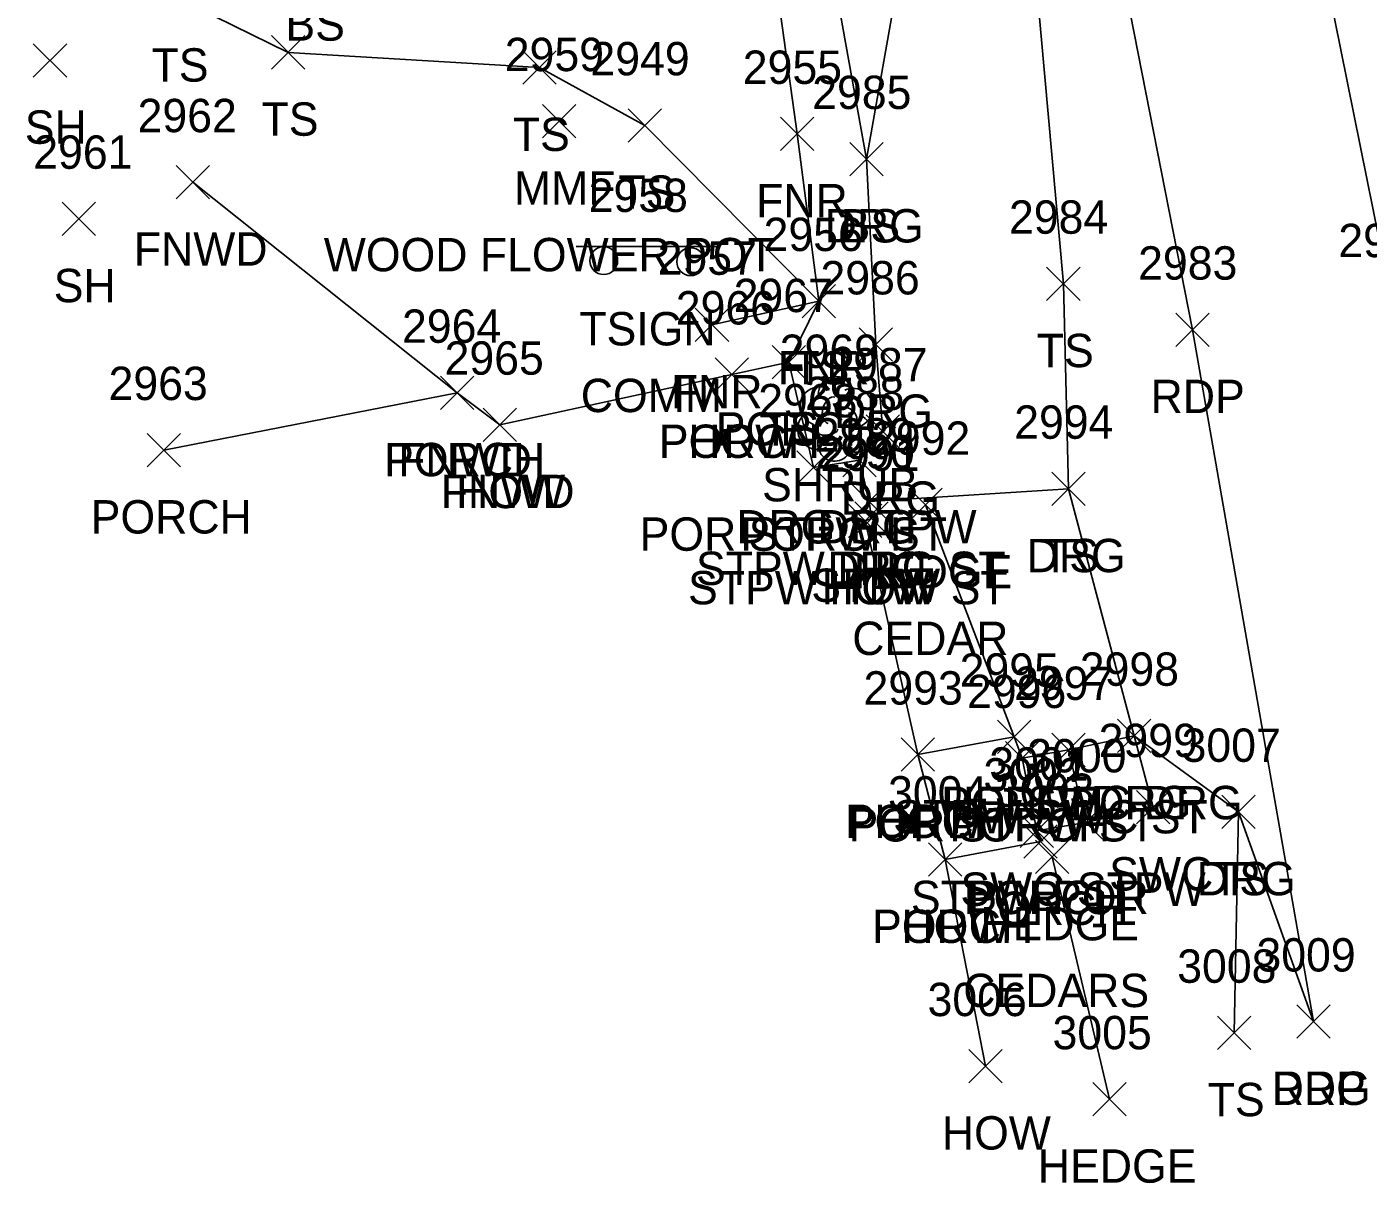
# Model space of a CAD drawing. Extents: x 1504228 to 1506103, y 437717 to 440106.
# Drawn here: x 1505191.7 to 1505272.1, y 437902.8 to 437972.2 of the extents above; entities that cross this region are included whole.
import ezdxf

# ---------------------------------------------------------------- set-up
doc = ezdxf.new("R2010")
doc.units = 0
for name, color, linetype in [('L_A', 7, 'Continuous'), ('L_C', 7, 'Continuous'), ('L_I', 7, 'Continuous'), ('L_TIC', 7, 'Continuous'), ('LAHR', 7, 'Continuous'), ('LBC', 7, 'Continuous'), ('LBF', 7, 'Continuous'), ('LELB', 7, 'Continuous'), ('LFNC', 7, 'Continuous'), ('LSH', 7, 'Continuous'), ('P_A', 7, 'Continuous'), ('P_I', 7, 'Continuous'), ('P_TIC', 7, 'Continuous'), ('PET', 7, 'Continuous'), ('PRC', 7, 'Continuous'), ('R_A', 7, 'Continuous'), ('R_I', 7, 'Continuous'), ('R_TIC', 7, 'Continuous'), ('RDG', 7, 'Continuous'), ('RSW', 7, 'Continuous'), ('S_A', 7, 'Continuous'), ('S_C', 7, 'Continuous'), ('S_I', 7, 'Continuous'), ('SSGN', 7, 'Continuous')]:
    doc.layers.add(name, color=color, linetype=linetype)

msp = doc.modelspace()

# ---------------------------------------------------------------- linework, layer by layer
at = {"layer": 'L_TIC'}
for points in [[(1505192.056, 437969.158), (1505194.056, 437971.158)], [(1505194.056, 437969.158), (1505192.056, 437971.158)], [(1505206.329, 437969.64), (1505208.329, 437971.64)], [(1505208.329, 437969.64), (1505206.329, 437971.64)], [(1505221.396, 437968.728), (1505223.396, 437970.728)], [(1505223.396, 437968.728), (1505221.396, 437970.728)], [(1505222.587, 437965.513), (1505224.587, 437967.513)], [(1505224.587, 437965.513), (1505222.587, 437967.513)], [(1505227.724, 437965.261), (1505229.724, 437967.261)], [(1505229.724, 437965.261), (1505227.724, 437967.261)], [(1505236.851, 437964.748), (1505238.851, 437966.748)], [(1505238.851, 437964.748), (1505236.851, 437966.748)], [(1505241.012, 437963.241), (1505243.012, 437965.241)], [(1505243.012, 437963.241), (1505241.012, 437965.241)], [(1505200.614, 437961.852), (1505202.614, 437963.852)], [(1505202.614, 437961.852), (1505200.614, 437963.852)], [(1505193.79, 437959.659), (1505195.79, 437961.659)], [(1505195.79, 437959.659), (1505193.79, 437961.659)], [(1505252.81, 437955.765), (1505254.81, 437957.765)], [(1505254.81, 437955.765), (1505252.81, 437957.765)], [(1505238.153, 437954.727), (1505240.153, 437956.727)], [(1505240.153, 437954.727), (1505238.153, 437956.727)], [(1505238.153, 437954.727), (1505240.153, 437956.727)], [(1505240.153, 437954.727), (1505238.153, 437956.727)], [(1505231.745, 437953.304), (1505233.745, 437955.304)], [(1505233.745, 437953.304), (1505231.745, 437955.304)], [(1505236.349, 437951.065), (1505238.349, 437953.065)], [(1505238.349, 437951.065), (1505236.349, 437953.065)], [(1505236.349, 437951.065), (1505238.349, 437953.065)], [(1505238.349, 437951.065), (1505236.349, 437953.065)], [(1505232.936, 437950.323), (1505234.936, 437952.323)], [(1505234.936, 437950.323), (1505232.936, 437952.323)], [(1505232.936, 437950.323), (1505234.936, 437952.323)], [(1505234.936, 437950.323), (1505232.936, 437952.323)], [(1505216.468, 437949.226), (1505218.468, 437951.226)], [(1505218.468, 437949.226), (1505216.468, 437951.226)], [(1505216.468, 437949.226), (1505218.468, 437951.226)], [(1505218.468, 437949.226), (1505216.468, 437951.226)], [(1505219.019, 437947.314), (1505221.019, 437949.314)], [(1505221.019, 437947.314), (1505219.019, 437949.314)], [(1505219.019, 437947.314), (1505221.019, 437949.314)], [(1505221.019, 437947.314), (1505219.019, 437949.314)], [(1505198.873, 437945.793), (1505200.873, 437947.793)], [(1505200.873, 437945.793), (1505198.873, 437947.793)], [(1505240.583, 437945.196), (1505242.583, 437947.196)], [(1505242.583, 437945.196), (1505240.583, 437947.196)], [(1505237.824, 437944.759), (1505239.824, 437946.759)], [(1505239.824, 437944.759), (1505237.824, 437946.759)], [(1505237.824, 437944.759), (1505239.824, 437946.759)], [(1505239.824, 437944.759), (1505237.824, 437946.759)], [(1505253.123, 437943.473), (1505255.123, 437945.473)], [(1505255.123, 437943.473), (1505253.123, 437945.473)], [(1505241.169, 437942.707), (1505243.169, 437944.707)], [(1505243.169, 437942.707), (1505241.169, 437944.707)], [(1505244.54, 437942.511), (1505246.54, 437944.511)], [(1505246.54, 437942.511), (1505244.54, 437944.511)], [(1505240.93, 437941.546), (1505242.93, 437943.546)], [(1505242.93, 437941.546), (1505240.93, 437943.546)], [(1505240.93, 437941.546), (1505242.93, 437943.546)], [(1505242.93, 437941.546), (1505240.93, 437943.546)], [(1505241.304, 437941.69), (1505243.304, 437943.69)], [(1505243.304, 437941.69), (1505241.304, 437943.69)], [(1505249.854, 437928.607), (1505251.854, 437930.607)], [(1505251.854, 437928.607), (1505249.854, 437930.607)], [(1505249.854, 437928.607), (1505251.854, 437930.607)], [(1505251.854, 437928.607), (1505249.854, 437930.607)], [(1505244.09, 437927.537), (1505246.09, 437929.537)], [(1505246.09, 437927.537), (1505244.09, 437929.537)], [(1505244.09, 437927.537), (1505246.09, 437929.537)], [(1505246.09, 437927.537), (1505244.09, 437929.537)], [(1505250.35, 437927.329), (1505252.35, 437929.329)], [(1505252.35, 437927.329), (1505250.35, 437929.329)], [(1505250.35, 437927.329), (1505252.35, 437929.329)], [(1505252.35, 437927.329), (1505250.35, 437929.329)], [(1505253.117, 437927.815), (1505255.117, 437929.815)], [(1505255.117, 437927.815), (1505253.117, 437929.815)], [(1505263.316, 437924.103), (1505265.316, 437926.103)], [(1505265.316, 437924.103), (1505263.316, 437926.103)], [(1505254.148, 437923.471), (1505256.148, 437925.471)], [(1505256.148, 437923.471), (1505254.148, 437925.471)], [(1505251.222, 437922.976), (1505253.222, 437924.976)], [(1505253.222, 437922.976), (1505251.222, 437924.976)], [(1505251.222, 437922.976), (1505253.222, 437924.976)], [(1505253.222, 437922.976), (1505251.222, 437924.976)], [(1505251.437, 437922.326), (1505253.437, 437924.326)], [(1505253.437, 437922.326), (1505251.437, 437924.326)], [(1505245.719, 437921.245), (1505247.719, 437923.245)], [(1505247.719, 437921.245), (1505245.719, 437923.245)], [(1505245.719, 437921.245), (1505247.719, 437923.245)], [(1505247.719, 437921.245), (1505245.719, 437923.245)], [(1505252.132, 437921.401), (1505254.132, 437923.401)], [(1505254.132, 437921.401), (1505252.132, 437923.401)], [(1505263.054, 437910.858), (1505265.054, 437912.858)], [(1505265.054, 437910.858), (1505263.054, 437912.858)], [(1505248.143, 437908.86), (1505250.143, 437910.86)], [(1505250.143, 437908.86), (1505248.143, 437910.86)], [(1505255.58, 437906.873), (1505257.58, 437908.873)], [(1505257.58, 437906.873), (1505255.58, 437908.873)]]:
    msp.add_lwpolyline(points, dxfattribs=at)
at = {"layer": 'LAHR'}
for points in [[(1505245.54, 437943.511), (1505250.854, 437929.607)], [(1505253.132, 437922.401), (1505256.58, 437907.873)]]:
    msp.add_lwpolyline(points, dxfattribs=at)
at = {"layer": 'LBC'}
for points in [[(1505220.019, 437948.314), (1505233.936, 437951.323)], [(1505241.93, 437942.546), (1505245.09, 437928.537), (1505246.719, 437922.245), (1505249.143, 437909.86)]]:
    msp.add_lwpolyline(points, dxfattribs=at)
at = {"layer": 'LBF'}
for points in [[(1505233.936, 437951.323), (1505237.349, 437952.065), (1505238.824, 437945.759)], [(1505199.873, 437946.793), (1505217.468, 437950.226)], [(1505238.824, 437945.759), (1505241.583, 437946.196), (1505242.169, 437943.707), (1505242.304, 437942.69), (1505241.93, 437942.546)], [(1505245.09, 437928.537), (1505250.854, 437929.607), (1505251.35, 437928.329), (1505252.222, 437923.976), (1505252.437, 437923.326), (1505246.719, 437922.245)], [(1505251.35, 437928.329), (1505254.117, 437928.815), (1505255.148, 437924.471), (1505252.222, 437923.976)]]:
    msp.add_lwpolyline(points, dxfattribs=at)
at = {"layer": 'LELB'}
for points in [[(1505216.601, 438137.556), (1505223.944, 438121.386), (1505226.122, 438115.183), (1505227.826, 438097.732), (1505234.433, 438067.787), (1505241.158, 438043.279), (1505244.446, 438026.005), (1505250.203, 437996.886), (1505253.81, 437956.765), (1505254.123, 437944.473)], [(1505216.575, 438127.724), (1505214.625, 438113.719), (1505216.782, 438101.678), (1505215.58, 438085.68), (1505222.54, 438071.184), (1505228.277, 438057.902), (1505236.701, 438043.311), (1505240.058, 438029.465), (1505242.84, 438013.821), (1505243.246, 437995.871), (1505245.516, 437984.141), (1505242.012, 437964.241)], [(1505200.521, 437982.869), (1505200.733, 437973.884), (1505207.329, 437970.64), (1505222.396, 437969.728), (1505228.724, 437966.261), (1505239.153, 437955.727), (1505237.349, 437952.065)], [(1505264.316, 437925.103), (1505264.054, 437911.858)]]:
    msp.add_lwpolyline(points, dxfattribs=at)
at = {"layer": 'LFNC'}
for points in [[(1505193.634, 437989.407), (1505201.282, 437990.707), (1505219.361, 437993.839), (1505234.026, 437996.905), (1505235.671, 437981.467), (1505237.851, 437965.748), (1505239.153, 437955.727), (1505232.745, 437954.304)], [(1505201.614, 437962.852), (1505217.468, 437950.226), (1505220.019, 437948.314)]]:
    msp.add_lwpolyline(points, dxfattribs=at)
at = {"layer": 'LSH'}
msp.add_line((1505240.119, 437948.719), (1505240.119, 437948.719), dxfattribs=at)
msp.add_line((1505240.119, 437948.719), (1505240.119, 437948.719), dxfattribs=at)
msp.add_arc((1505240.166, 437950.153), 1.047, 335.52715, 180.95627, dxfattribs=at)
for centre, major_axis, ratio, start_param, end_param in [((1505239.328, 437949.386), (1.21, -0.512), 0.895232, 1.570796, 4.712389), ((1505241.161, 437949.303), (-1.141, -0.483), 0.949671, 1.570796, 4.712389), ((1505239.911, 437949.178), (-0.208, -0.792), 0.645439, 3.141593, 6.283185), ((1505240.619, 437948.553), (-0.5, 0.667), 0.989748, 3.141593, 6.283185), ((1505239.036, 437948.011), (0.584, -1.042), 0.959034, 3.141593, 6.283185), ((1505241.119, 437947.886), (-1.09, 0.792), 0.841452, 1.570796, 4.712389), ((1505239.661, 437947.969), (-0.625, -0.083), 0.423636, 0, 3.141593), ((1505240.12, 437947.219), (0.265, 1.061), 0.942809, 1.570796, 4.712389)]:
    msp.add_ellipse(centre, major_axis=major_axis, ratio=ratio, start_param=start_param, end_param=end_param, dxfattribs=at)
at = {"layer": 'P_TIC'}
for points in [[(1505260.553, 437953.013), (1505262.553, 437955.013)], [(1505262.553, 437953.013), (1505260.553, 437955.013)], [(1505267.813, 437911.533), (1505269.813, 437913.533)], [(1505269.813, 437911.533), (1505267.813, 437913.533)]]:
    msp.add_lwpolyline(points, dxfattribs=at)
at = {"layer": 'PET'}
msp.add_lwpolyline([(1505219.541, 438139.332), (1505225.977, 438121.196), (1505231.004, 438101.796), (1505238.496, 438063.959), (1505242.844, 438043.923), (1505252.224, 438001.481), (1505261.553, 437954.013), (1505268.813, 437912.533)], dxfattribs=at)
at = {"layer": 'PRC'}
msp.add_lwpolyline([(1505229.478, 438143.453), (1505234.695, 438118.095), (1505243.623, 438084.856), (1505253.152, 438053.473), (1505260.454, 438023.846), (1505266.195, 437991.874), (1505273.558, 437955.361), (1505281.379, 437913.196)], dxfattribs=at)
at = {"layer": 'R_TIC'}
for points in [[(1505241.012, 437963.241), (1505243.012, 437965.241)], [(1505243.012, 437963.241), (1505241.012, 437965.241)], [(1505241.564, 437952.127), (1505243.564, 437954.127)], [(1505243.564, 437952.127), (1505241.564, 437954.127)], [(1505241.98, 437946.915), (1505243.98, 437948.915)], [(1505243.98, 437946.915), (1505241.98, 437948.915)], [(1505240.583, 437945.196), (1505242.583, 437947.196)], [(1505242.583, 437945.196), (1505240.583, 437947.196)], [(1505253.123, 437943.473), (1505255.123, 437945.473)], [(1505255.123, 437943.473), (1505253.123, 437945.473)], [(1505241.169, 437942.707), (1505243.169, 437944.707)], [(1505243.169, 437942.707), (1505241.169, 437944.707)], [(1505257.054, 437928.664), (1505259.054, 437930.664)], [(1505259.054, 437928.664), (1505257.054, 437930.664)], [(1505257.054, 437928.664), (1505259.054, 437930.664)], [(1505259.054, 437928.664), (1505257.054, 437930.664)], [(1505253.117, 437927.815), (1505255.117, 437929.815)], [(1505255.117, 437927.815), (1505253.117, 437929.815)], [(1505258.195, 437924.39), (1505260.195, 437926.39)], [(1505260.195, 437924.39), (1505258.195, 437926.39)], [(1505263.316, 437924.103), (1505265.316, 437926.103)], [(1505265.316, 437924.103), (1505263.316, 437926.103)], [(1505254.148, 437923.471), (1505256.148, 437925.471)], [(1505256.148, 437923.471), (1505254.148, 437925.471)], [(1505267.813, 437911.533), (1505269.813, 437913.533)], [(1505269.813, 437911.533), (1505267.813, 437913.533)]]:
    msp.add_lwpolyline(points, dxfattribs=at)
at = {"layer": 'RDG'}
for points in [[(1505252.224, 438001.481), (1505250.203, 437996.886), (1505245.516, 437984.141), (1505239.029, 437980.808), (1505242.012, 437964.241), (1505242.564, 437953.127), (1505242.98, 437947.915), (1505241.583, 437946.196)], [(1505242.169, 437943.707), (1505254.123, 437944.473), (1505258.054, 437929.664), (1505264.316, 437925.103), (1505268.813, 437912.533)]]:
    msp.add_lwpolyline(points, dxfattribs=at)
at = {"layer": 'RSW'}
msp.add_lwpolyline([(1505254.117, 437928.815), (1505258.054, 437929.664), (1505259.195, 437925.39), (1505255.148, 437924.471)], dxfattribs=at)
at = {"layer": 'SSGN'}
for p, q in [((1505224.593, 437958.991), (1505233.19, 437958.991)), ((1505228.615, 437958.087), (1505228.615, 437958.087))]:
    msp.add_line(p, q, dxfattribs=at)
for centre in [(1505226.254, 437958.158), (1505231.469, 437958.087)]:
    msp.add_circle(centre, 0.833, dxfattribs=at)

# ---------------------------------------------------------------- texts
at = {"layer": 'L_A'}
for s, p in [('BS', (1505207.169, 437971.338)), ('TS', (1505199.143, 437968.884)), ('SH', (1505191.545, 437965.158)), ('TS', (1505205.738, 437965.64)), ('TS', (1505220.805, 437964.728)), ('MMF', (1505220.871, 437961.513)), ('TS', (1505227.133, 437961.261)), ('FNR', (1505235.387, 437960.748)), ('BS', (1505240.453, 437959.241)), ('FNWD', (1505198.079, 437957.852)), ('SH', (1505193.278, 437955.659)), ('TS', (1505252.22, 437951.765)), ('FNR', (1505236.689, 437950.727)), ('TS', (1505237.563, 437950.727)), ('FNR', (1505230.281, 437949.304)), ('PORCH', (1505232.971, 437947.065)), ('TS', (1505235.758, 437947.065)), ('PORCH', (1505229.558, 437946.323)), ('HOW', (1505231.322, 437946.323)), ('PORCH', (1505213.09, 437945.226)), ('FNWD', (1505213.933, 437945.226)), ('SHRUB', (1505235.749, 437943.719)), ('FNWD', (1505216.483, 437943.314)), ('HOW', (1505217.405, 437943.314)), ('PORCH', (1505195.495, 437941.793)), ('DRG STPW', (1505234.197, 437941.196)), ('POR STPW ST', (1505228.406, 437940.759)), ('PORCH', (1505234.446, 437940.759)), ('TS', (1505252.532, 437939.473)), ('STPW DRG ST', (1505231.783, 437938.707)), ('HEDGE', (1505241.241, 437938.511)), ('STPW HOW ST', (1505231.308, 437937.546)), ('STPW', (1505238.698, 437937.69)), ('HOW', (1505239.316, 437937.546)), ('PORCH', (1505246.476, 437924.607)), ('HEDGE', (1505246.555, 437924.607)), ('PORCH', (1505240.712, 437923.537)), ('POR STPW ST', (1505240.933, 437923.329)), ('HOW', (1505242.476, 437923.537)), ('STPW SWC ST', (1505243.605, 437923.815)), ('PORCH', (1505246.972, 437923.329)), ('TS', (1505262.725, 437920.103)), ('SWC STPW', (1505247.636, 437919.471)), ('STPW POR', (1505244.671, 437918.976)), ('PORCH', (1505247.844, 437918.976)), ('PORCH', (1505248.059, 437918.326)), ('PORCH', (1505242.341, 437917.245)), ('HOW', (1505244.104, 437917.245)), ('HEDGE', (1505248.833, 437917.401)), ('TS', (1505262.464, 437906.858)), ('HOW', (1505246.529, 437904.86)), ('HEDGE', (1505252.281, 437902.873))]:
    msp.add_text(s, height=2, dxfattribs=at).set_placement(p)
at = {"layer": 'L_C'}
for s, p in [('WOOD FLOWER POT', (1505209.469, 437957.513)), ('CEDAR', (1505241.154, 437934.511)), ('CEDARS', (1505247.809, 437913.401))]:
    msp.add_text(s, height=2, dxfattribs=at).set_placement(p)
at = {"layer": 'L_I'}
for s, p in [('2959', (1505220.32, 437969.513)), ('2949', (1505225.456, 437969.261)), ('2955', (1505234.591, 437968.748)), ('2985', (1505238.752, 437967.241)), ('2962', (1505198.307, 437965.852)), ('2961', (1505192.05, 437963.659)), ('2984', (1505250.551, 437959.765)), ('2956', (1505235.838, 437958.727)), ('2956', (1505235.838, 437958.727)), ('2957', (1505229.485, 437957.304)), ('2967', (1505234.042, 437955.065)), ('2967', (1505234.042, 437955.065)), ('2966', (1505230.574, 437954.323)), ('2966', (1505230.574, 437954.323)), ('2964', (1505214.161, 437953.226)), ('2964', (1505214.161, 437953.226)), ('2969', (1505236.804, 437951.719)), ('2965', (1505216.712, 437951.314)), ('2965', (1505216.712, 437951.314)), ('2963', (1505196.566, 437949.793)), ('2988', (1505238.323, 437949.196)), ('2968', (1505235.517, 437948.759)), ('2968', (1505235.517, 437948.759)), ('2994', (1505250.863, 437947.473)), ('2989', (1505238.901, 437946.707)), ('2992', (1505242.28, 437946.511)), ('2990', (1505238.958, 437945.69)), ('2991', (1505239.237, 437945.546)), ('2991', (1505239.237, 437945.546)), ('2995', (1505247.594, 437932.607)), ('2995', (1505247.594, 437932.607)), ('2993', (1505241.83, 437931.537)), ('2993', (1505241.83, 437931.537)), ('2996', (1505248.035, 437931.329)), ('2996', (1505248.035, 437931.329)), ('2997', (1505250.857, 437931.815)), ('3007', (1505260.899, 437928.103)), ('3000', (1505251.644, 437927.471)), ('3001', (1505249.372, 437926.976)), ('3001', (1505249.372, 437926.976)), ('3002', (1505249.019, 437926.326)), ('3004', (1505243.301, 437925.245)), ('3004', (1505243.301, 437925.245)), ('3003', (1505249.714, 437925.401)), ('3008', (1505260.637, 437914.858)), ('3006', (1505245.67, 437912.86)), ('3005', (1505253.163, 437910.873))]:
    msp.add_text(s, height=2, dxfattribs=at).set_placement(p)
at = {"layer": 'P_A'}
for p in [(1505259.041, 437949.013), (1505266.302, 437907.533)]:
    msp.add_text('RDP', height=2, dxfattribs=at).set_placement(p)
at = {"layer": 'P_I'}
for s, p in [('2982', (1505270.298, 437958.361)), ('2983', (1505258.293, 437957.013)), ('3009', (1505265.388, 437915.533))]:
    msp.add_text(s, height=2, dxfattribs=at).set_placement(p)
at = {"layer": 'R_A'}
for s, p in [('DRG', (1505239.5, 437959.241)), ('DRG', (1505240.052, 437948.127)), ('DRG', (1505240.468, 437942.915)), ('DRG', (1505239.071, 437941.196)), ('DRG', (1505251.611, 437939.473)), ('DRG', (1505239.657, 437938.707)), ('SWC DRG', (1505251.636, 437924.664)), ('DRG', (1505255.542, 437924.664)), ('STPW SWC ST', (1505243.605, 437923.815)), ('SWC', (1505256.557, 437920.39)), ('DRG', (1505261.804, 437920.103)), ('SWC STPW', (1505247.636, 437919.471)), ('DRG', (1505266.302, 437907.533))]:
    msp.add_text(s, height=2, dxfattribs=at).set_placement(p)
at = {"layer": 'R_I'}
for s, p in [('2985', (1505238.752, 437967.241)), ('2986', (1505239.249, 437956.127)), ('2987', (1505239.72, 437950.915)), ('2988', (1505238.323, 437949.196)), ('2994', (1505250.863, 437947.473)), ('2989', (1505238.901, 437946.707)), ('2998', (1505254.794, 437932.664)), ('2998', (1505254.794, 437932.664)), ('2997', (1505250.857, 437931.815)), ('2999', (1505255.927, 437928.39)), ('3007', (1505260.899, 437928.103)), ('3000', (1505251.644, 437927.471)), ('3009', (1505265.388, 437915.533))]:
    msp.add_text(s, height=2, dxfattribs=at).set_placement(p)
at = {"layer": 'S_A'}
msp.add_text('TSIGN', height=2, dxfattribs=at).set_placement((1505224.791, 437953.07))
at = {"layer": 'S_C'}
msp.add_text('COMM', height=2, dxfattribs=at).set_placement((1505224.878, 437949.07))
at = {"layer": 'S_I'}
msp.add_text('2958', height=2, dxfattribs=at).set_placement((1505225.35, 437961.07))

doc.saveas('drawing.dxf')
